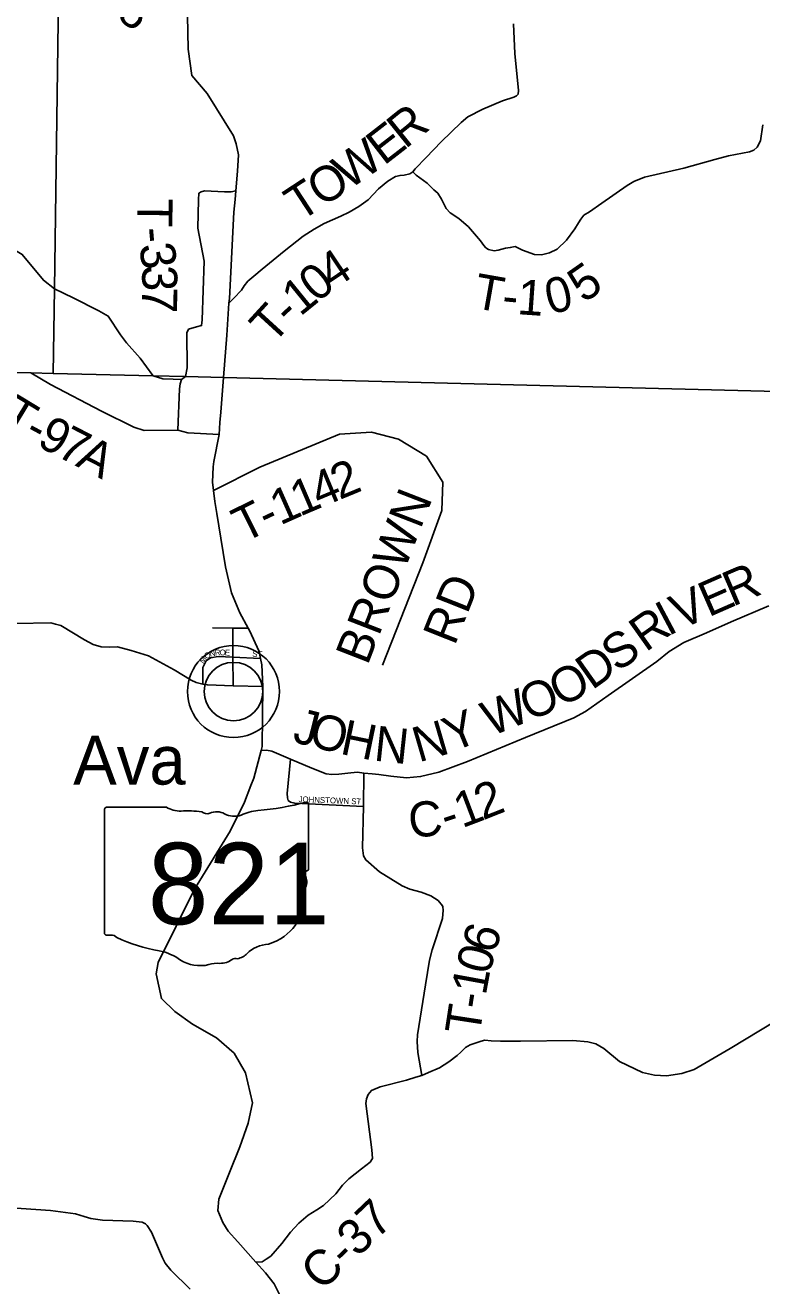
# Model space of a CAD drawing. Extents: x -22 to 431, y -18 to 160.
# Drawn here: x 322.192 to 323.383, y 151.4 to 153.438 of the extents above; entities that cross this region are included whole.
import ezdxf

# ---------------------------------------------------------------- set-up
doc = ezdxf.new("R2010")
doc.units = 0
for name, color, linetype in [('GM_X_Adjacent_County', 7, 'Continuous'), ('GM_X_Adjacent_County_Text', 7, 'Continuous'), ('GM_X_Airport_Location_Class_2', 7, 'Continuous'), ('GM_X_City_Street', 7, 'Continuous'), ('GM_X_City_Street_Text', 7, 'Continuous'), ('GM_X_County_ROW', 7, 'Continuous'), ('GM_X_County_Subdivision', 7, 'Continuous'), ('GM_X_Major_River_Text', 7, 'Continuous'), ('GM_X_Minor_River_Text', 7, 'Continuous'), ('GM_X_Township_Road', 7, 'Continuous'), ('GM_X_Township_ROW', 7, 'Continuous')]:
    doc.layers.add(name, color=color, linetype=linetype)

msp = doc.modelspace()

# ---------------------------------------------------------------- linework, layer by layer
at = {"layer": 'GM_X_Adjacent_County_Text'}
for points in [[(322.5737, 152.2656), (322.5826, 152.2661), (322.5909, 152.2643), (322.6214, 152.2513), (322.6559, 152.2371), (322.6787, 152.2278), (322.6881, 152.2267), (322.6991, 152.2272), (322.7188, 152.2296), (322.7294, 152.2305), (322.7396, 152.229), (322.7529, 152.2276), (322.7639, 152.2266), (322.7832, 152.2241), (322.8086, 152.2216), (322.8313, 152.2233), (322.8611, 152.2307), (322.9072, 152.2478), (323.0012, 152.2868), (323.0793, 152.3186), (323.0982, 152.3286), (323.1344, 152.3543), (323.2135, 152.4095), (323.2334, 152.4256), (323.2572, 152.4399), (323.2938, 152.4557), (323.3334, 152.4738), (323.3942, 152.4994)], [(322.1771, 152.4707), (322.2339, 152.4717), (322.2411, 152.4699), (322.2499, 152.4674), (322.2882, 152.4446), (322.3023, 152.4369), (322.3149, 152.4329), (322.3281, 152.4328), (322.3414, 152.433), (322.3638, 152.427), (322.3916, 152.4187), (322.4329, 152.396), (322.4605, 152.3794), (322.4689, 152.3753), (322.4797, 152.373), (322.4868, 152.3715), (322.5284, 152.3703), (322.5762, 152.3689)], [(322.565, 151.4381), (322.5753, 151.4387), (322.5821, 151.4433), (322.5893, 151.4482), (322.6071, 151.4688), (322.6211, 151.4866), (322.6347, 151.5014), (322.6498, 151.5144), (322.6635, 151.5231), (322.6744, 151.5299), (322.6945, 151.5489), (322.7051, 151.5626), (322.7153, 151.5733), (322.7361, 151.5892), (322.7501, 151.6002), (322.7535, 151.6059), (322.7528, 151.62), (322.7428, 151.6951), (322.744, 151.7023), (322.7466, 151.7095), (322.7519, 151.716), (322.7659, 151.722), (322.8087, 151.7327), (322.8235, 151.7373), (322.8337, 151.7404), (322.8443, 151.7449), (322.8621, 151.7525), (322.8772, 151.762), (322.8908, 151.7723), (322.8965, 151.778), (322.9041, 151.7852), (322.9116, 151.7898), (322.9291, 151.7959), (322.9351, 151.7974), (322.9453, 151.7963), (322.9605, 151.7956), (322.993, 151.7956), (323.0775, 151.7965), (323.1017, 151.7946), (323.1146, 151.7916), (323.1275, 151.7837), (323.1532, 151.7628), (323.1904, 151.7451), (323.2097, 151.7409), (323.229, 151.7398), (323.2536, 151.7433), (323.2737, 151.7497), (323.3316, 151.7836), (323.43, 151.8429)]]:
    msp.add_lwpolyline(points, dxfattribs=at)
at = {"layer": 'GM_X_Airport_Location_Class_2'}
for p, q in [((322.4205, 152.1739), (322.3239, 152.1739)), ((322.6503, 152.0742), (322.6503, 152.1789)), ((322.3207, 152.1705), (322.3207, 151.9704)), ((322.6503, 152.0742), (322.6503, 152.0742))]:
    msp.add_line(p, q, dxfattribs=at)
for centre, major_axis, start_param, end_param in [((322.3245, 152.1709), (0.00382, 0), 1.712693, 3.28349), ((322.4435, 152.1971), (0.037, 0), 4.042523, 4.731795), ((322.5329, 152.4467), (0.3495, 0), 4.814394, 5.042369), ((322.6466, 152.1793), (0.00367, 0), 6.141152, 7.989035), ((322.4557, 152.0616), (0.133, 0), 1.404758, 1.657858), ((322.4859, 152.1719), (0.0107, 0), 3.836095, 5.185415), ((322.5016, 152.1488), (0.0222, 0), 0.950623, 2.079405), ((322.5303, 152.1805), (0.0267, 0), 4.081561, 5.145723), ((322.5775, 152.1128), (0.0703, 0), 1.699011, 2.107814), ((322.6464, 152.0738), (0.00393, 0), 5.05454, 6.418171), ((322.6494, 152.0665), (0.00568, 0), 1.883978, 3.671073), ((322.6133, 152.0533), (0.0341, 0), 5.934695, 6.695948), ((322.6634, 152.0304), (0.0248, 0), 2.387724, 3.262537), ((322.5525, 152.0171), (0.0874, 0), 5.101752, 6.440018), ((322.3245, 151.9699), (0.00385, 0), 3.00124, 4.508301), ((322.3251, 151.9904), (0.0294, 0), 4.665946, 4.897461), ((322.3311, 151.9588), (0.0106, 0), 0.519207, 1.627899), ((322.4649, 152.1386), (0.2524, 0), 4.195997, 4.488961), ((322.5893, 151.9142), (0.0479, 0), 1.647645, 2.488434), ((322.3897, 151.8804), (0.079, 0), 0.823519, 1.323587), ((322.5319, 151.9234), (0.00752, 0), 1.147584, 2.315152), ((322.5287, 151.951), (0.0282, 0), 4.937069, 5.64225), ((322.4751, 151.9578), (0.0501, 0), 4.026481, 4.996735), ((322.5041, 151.8886), (0.0412, 0), 1.495662, 1.94098), ((322.5077, 151.9428), (0.0267, 0), 4.691044, 5.507374)]:
    msp.add_ellipse(centre, major_axis=major_axis, ratio=0.8, start_param=start_param, end_param=end_param, dxfattribs=at)
at = {"layer": 'GM_X_County_ROW'}
for points in [[(322.5071, 152.7956), (322.5083, 152.8125), (322.5131, 152.8688), (322.5183, 152.9368), (322.5213, 152.9886), (322.5225, 152.9965), (322.5295, 153.1359), (322.5316, 153.1564), (322.5328, 153.1703), (322.5354, 153.202), (322.537, 153.2284), (322.5333, 153.2465), (322.5292, 153.2593), (322.4867, 153.3278), (322.4619, 153.3569), (322.4557, 153.3994), (322.4547, 153.4537)], [(322.5572, 152.2089), (322.5619, 152.2209), (322.5737, 152.2656), (322.5753, 152.2719), (322.5762, 152.3689), (322.5747, 152.4043), (322.5728, 152.4142), (322.5707, 152.4254), (322.5548, 152.4593), (322.5526, 152.4634), (322.5392, 152.4882), (322.5258, 152.5204), (322.5162, 152.5625), (322.5084, 152.6091), (322.5023, 152.6485), (322.4991, 152.6683), (322.4967, 152.6861), (322.495, 152.6992), (322.4962, 152.7241), (322.4974, 152.7326), (322.5057, 152.7763), (322.5071, 152.7956)], [(322.6129, 151.3667), (322.595, 151.4031), (322.581, 151.4209), (322.565, 151.4381), (322.5363, 151.4713), (322.5204, 151.4887), (322.5119, 151.5025), (322.5035, 151.5218), (322.5053, 151.5404), (322.5226, 151.5831), (322.5391, 151.6249), (322.553, 151.663), (322.5597, 151.6961), (322.5485, 151.7446), (322.5302, 151.7761), (322.5016, 151.801), (322.4628, 151.8232), (322.4343, 151.8436), (322.4126, 151.8644), (322.4038, 151.9044), (322.4075, 151.9226), (322.4658, 152.0416), (322.5235, 152.1353), (322.5468, 152.1821), (322.5572, 152.2089)]]:
    msp.add_lwpolyline(points, dxfattribs=at)
at = {"layer": 'GM_X_Major_River_Text'}
for p, q in [((322.2395, 153.0117), (322.2483, 153.6572)), ((322.2375, 152.875), (322.2395, 153.0117)), ((322.2375, 152.875), (322.2395, 153.0117)), ((322.2014, 152.8759), (321.8466, 152.8811)), ((322.2375, 152.875), (322.2014, 152.8759)), ((322.3991, 152.8714), (322.2375, 152.875)), ((322.4515, 152.8702), (322.3991, 152.8714)), ((322.5131, 152.8688), (322.4515, 152.8702)), ((323.9452, 152.8321), (322.5131, 152.8688))]:
    msp.add_line(p, q, dxfattribs=at)
at = {"layer": 'GM_X_Minor_River_Text'}
for points in [[(322.5213, 152.9886), (322.5294, 152.9966), (322.5418, 153.01), (322.5463, 153.0169), (322.5523, 153.0245), (322.5621, 153.0326), (322.5756, 153.0437), (322.611, 153.0728), (322.6419, 153.0969), (322.6596, 153.1084), (322.6754, 153.1173), (322.7026, 153.1296), (322.7162, 153.1358), (322.7316, 153.145), (322.7467, 153.1558), (322.7636, 153.1737), (322.7783, 153.186), (322.7907, 153.1933), (322.7983, 153.1952), (322.8051, 153.1957), (322.8138, 153.1976), (322.8191, 153.2011), (322.8225, 153.2057), (322.8405, 153.2244), (322.8645, 153.2496), (322.8807, 153.2653), (322.8969, 153.281), (322.9078, 153.2898), (322.9319, 153.3025), (322.964, 153.3156), (322.9822, 153.3219), (322.9863, 153.3238), (322.9889, 153.3265), (322.9897, 153.3325), (322.9839, 153.3924), (322.9817, 153.4402)], [(322.8191, 153.2011), (322.8244, 153.1958), (322.8419, 153.1827), (322.8526, 153.1721), (322.8595, 153.1665), (322.8652, 153.1571), (322.8729, 153.142), (322.879, 153.1348), (322.8934, 153.1254), (322.9091, 153.1119), (322.9285, 153.0897), (322.9335, 153.0821), (322.9369, 153.0784), (322.9411, 153.0754), (322.9502, 153.0735), (322.957, 153.0744), (322.9687, 153.0779), (322.9763, 153.0787), (322.9842, 153.0803), (322.996, 153.0743), (323.0154, 153.0672), (323.0267, 153.0669), (323.0396, 153.0701), (323.0524, 153.0759), (323.0675, 153.0904), (323.081, 153.1091), (323.0866, 153.1186), (323.0903, 153.1243), (323.0952, 153.1308), (323.1042, 153.1362), (323.1242, 153.1504), (323.1653, 153.1788), (323.1762, 153.1853), (323.1936, 153.1923), (323.2567, 153.2068), (323.307, 153.2209), (323.3293, 153.2267), (323.3633, 153.2335), (323.3701, 153.2362), (323.3757, 153.2408), (323.3806, 153.2514), (323.3846, 153.2773)], [(322.0912, 153.1875), (322.1061, 153.1655), (322.1129, 153.1463), (322.1145, 153.1392), (322.1211, 153.1321), (322.14, 153.1135), (322.1702, 153.0776), (322.1875, 153.0675), (322.2219, 153.0258), (322.2395, 153.0117)], [(322.5328, 153.1703), (322.5251, 153.169), (322.5145, 153.1688), (322.4823, 153.1701), (322.4767, 153.1688), (322.4729, 153.1665), (322.4723, 153.1559), (322.4716, 153.11), (322.4815, 153.0566), (322.4783, 152.9619), (322.4774, 152.9525), (322.4693, 152.9507), (322.4564, 152.9466), (322.4536, 152.9407), (322.4544, 152.8842), (322.4515, 152.8702), (322.4448, 152.8652)], [(322.3986, 152.872), (322.3779, 152.8999), (322.3562, 152.9244), (322.3465, 152.9378), (322.3265, 152.968), (322.3114, 152.9766), (322.2698, 152.9972), (322.2395, 153.0117)], [(322.2014, 152.8759), (322.2332, 152.8571), (322.3157, 152.814), (322.3678, 152.7882), (322.3846, 152.783), (322.4393, 152.7832)], [(322.4448, 152.8652), (322.4317, 152.866), (322.4146, 152.8664), (322.3991, 152.8714), (322.3986, 152.872)], [(322.5057, 152.7763), (322.4551, 152.7793), (322.4393, 152.7832), (322.4417, 152.8501), (322.4428, 152.8583), (322.4448, 152.8652)], [(322.4967, 152.6861), (322.5715, 152.7237), (322.7004, 152.7772), (322.7519, 152.7804), (322.7956, 152.7687), (322.8408, 152.7414), (322.8673, 152.6994), (322.8658, 152.6535), (322.8351, 152.5687), (322.7698, 152.4037)], [(322.7396, 152.229), (322.7391, 152.1751)], [(322.7391, 152.1751), (322.7391, 152.1751), (322.7378, 152.108), (322.739, 152.0955), (322.7429, 152.0887), (322.765, 152.0695), (322.8019, 152.0467), (322.814, 152.0414), (322.8326, 152.0363), (322.8478, 152.0307), (322.8596, 152.0232), (322.8668, 152.0142), (322.8676, 152.0126), (322.868, 152.0073), (322.8666, 151.994), (322.8503, 151.9435), (322.8459, 151.9264), (322.8393, 151.8868), (322.8267, 151.8059), (322.826, 151.7953), (322.8272, 151.7775), (322.8337, 151.7404)], [(322.1623, 151.5268), (322.2332, 151.522), (322.2739, 151.5167), (322.2879, 151.5124), (322.2982, 151.5088), (322.3172, 151.5061), (322.3669, 151.5047), (322.3813, 151.5031), (322.387, 151.5001), (322.3897, 151.4979), (322.3967, 151.4866), (322.4141, 151.4452), (322.4184, 151.4369), (322.4277, 151.4253), (322.4589, 151.3948)]]:
    msp.add_lwpolyline(points, dxfattribs=at)
at = {"layer": 'GM_X_Township_Road'}
for radius in [0.0744, 0.0472]:
    msp.add_circle((322.529, 152.3609), radius, dxfattribs=at)
at = {"layer": 'GM_X_Township_ROW'}
for points in [[(322.4949, 152.464), (322.5277, 152.4636), (322.5526, 152.4634)], [(322.5279, 152.4286), (322.5277, 152.4636)], [(322.5728, 152.4142), (322.528, 152.4166), (322.5044, 152.4178), (322.4916, 152.4153), (322.4848, 152.4107), (322.4794, 152.3996), (322.4797, 152.373)], [(322.5284, 152.3703), (322.528, 152.4166), (322.5279, 152.4286), (322.5279, 152.4286)], [(322.6214, 152.2513), (322.6157, 152.1962), (322.6165, 152.189), (322.6172, 152.1848), (322.6211, 152.1818), (322.6279, 152.1803), (322.7391, 152.1751)]]:
    msp.add_lwpolyline(points, dxfattribs=at)

# ---------------------------------------------------------------- texts
at = {"layer": 'GM_X_Adjacent_County'}
msp.add_text('Ava', height=0.07891, rotation=0, dxfattribs=at).set_placement((322.2699, 152.2105))
at = {"layer": 'GM_X_Airport_Location_Class_2'}
msp.add_text('821', height=0.13184, dxfattribs=at).set_placement((322.3905, 151.9845))
at = {"layer": 'GM_X_City_Street'}
for s, height, rotation, p in [('R', 0.0568, 23.2503, (323.3357, 152.4977)), ('E', 0.0568, 23.6966, (323.2969, 152.4806)), ('V', 0.0568, 24.1777, (323.2514, 152.4602)), ('I', 0.0568, 27.965, (323.2316, 152.4497)), ('R', 0.0568, 35.3725, (323.1952, 152.4237)), ('S', 0.0568, 35.1543, (323.1494, 152.3913)), ('D', 0.0568, 35.3468, (323.1086, 152.3624)), ('O', 0.0568, 28.7901, (323.0588, 152.3345)), ('O', 0.0568, 22.1968, (323.006, 152.3126)), ('W', 0.0568, 22.1138, (322.945, 152.2877)), ('J', 0.0568, 345.7633, (322.6227, 152.2799)), ('O', 0.0568, 345.8408, (322.6487, 152.2733)), ('Y', 0.0568, 22.2968, (322.8825, 152.2622)), ('H', 0.0568, 348.2621, (322.6997, 152.2605)), ('N', 0.0568, 353.7904, (322.7546, 152.2494)), ('N', 0.0568, 16.2301, (322.8283, 152.2461)), ('2', 0.0568, 21.5625, (322.932, 152.1524)), ('1', 0.0568, 20.7833, (322.8985, 152.1397)), ('C', 0.0568, 6.379, (322.8148, 152.1236)), ('-', 0.0568, 18.0411, (322.8735, 152.1315)), ('C-37', 0.05682, 43.571, (322.6714, 151.39))]:
    msp.add_text(s, height=height, rotation=rotation, dxfattribs=at).set_placement(p)
at = {"layer": 'GM_X_City_Street_Text'}
for s, height, rotation, p in [('8', 0.0568, 320.4581, (322.3376, 153.4526)), ('R', 0.0568, 38.8205, (322.8066, 153.237)), ('E', 0.0568, 37.779, (322.7722, 153.2103)), ('W', 0.0568, 34.4701, (322.715, 153.1709)), ('O', 0.0568, 33.1778, (322.672, 153.1428)), ('T', 0.0568, 33.1825, (322.6364, 153.1195)), ('T', 0.0568, 269.5586, (322.3738, 153.158)), ('-', 0.0568, 275.0908, (322.3737, 153.1095)), ('3', 0.0568, 278.5086, (322.3762, 153.0826)), ('4', 0.0568, 33.9888, (322.69, 153.0095)), ('0', 0.0568, 38.9321, (322.6638, 152.9883)), ('5', 0.0568, 35.045, (323.0953, 152.9879)), ('3', 0.0568, 270.6974, (322.3812, 153.05)), ('T', 0.0568, 349.9719, (322.915, 152.9815)), ('0', 0.0568, 13.4942, (323.0402, 152.9702)), ('7', 0.0568, 268.6989, (322.3817, 153.0156)), ('1', 0.0568, 39.0759, (322.6367, 152.9663)), ('1', 0.0568, 355.9871, (322.9865, 152.9711)), ('T', 0.0568, 47.607, (322.5926, 152.9205)), ('-', 0.0568, 354.5167, (322.9617, 152.9734)), ('-', 0.0568, 43.1396, (322.6205, 152.951)), ('T', 0.0568, 328.7628, (322.1491, 152.7942)), ('-', 0.0568, 331.7007, (322.1882, 152.7705)), ('9', 0.0568, 332.2211, (322.2092, 152.7592)), ('7', 0.0568, 332.6839, (322.2406, 152.7427)), ('A', 0.0568, 332.8402, (322.2719, 152.7265)), ('2', 0.0568, 22.4633, (322.7004, 152.6704)), ('1', 0.0568, 23.1186, (322.6361, 152.6433)), ('4', 0.0568, 22.6103, (322.6681, 152.657)), ('1', 0.0568, 23.9878, (322.6043, 152.6291)), ('BROWN', 0.05682, 68.7387, (322.7456, 152.4019)), ('T', 0.0568, 26.3312, (322.5456, 152.6006)), ('-', 0.0568, 25.1197, (322.5834, 152.6194)), ('RD', 0.05682, 68.289, (322.8865, 152.4336)), ('6', 0.0568, 73.4942, (322.9516, 151.9351)), ('0', 0.0568, 75.2506, (322.9428, 151.9017)), ('1', 0.0568, 79.5657, (322.9367, 151.8684)), ('-', 0.0568, 80.8918, (322.9331, 151.8457)), ('T', 0.0568, 81.2577, (322.9267, 151.8038))]:
    msp.add_text(s, height=height, rotation=rotation, dxfattribs=at).set_placement(p)
at = {"layer": 'GM_X_County_Subdivision'}
for s, rotation, p in [('M', 53.05, (322.48, 152.4053)), ('O', 33.187, (322.4853, 152.4127)), ('N', 12.8701, (322.4915, 152.4169)), ('R', 5.7154, (322.4993, 152.4187)), ('O', 359.1694, (322.5065, 152.4194)), ('E', 357.8961, (322.5148, 152.4193)), ('ST', 356.4262, (322.5592, 152.4172)), ('JOHNSTOWN ST', 357.8196, (322.6341, 152.1822))]:
    msp.add_text(s, height=0.00947, rotation=rotation, dxfattribs=at).set_placement(p)

doc.saveas('drawing.dxf')
